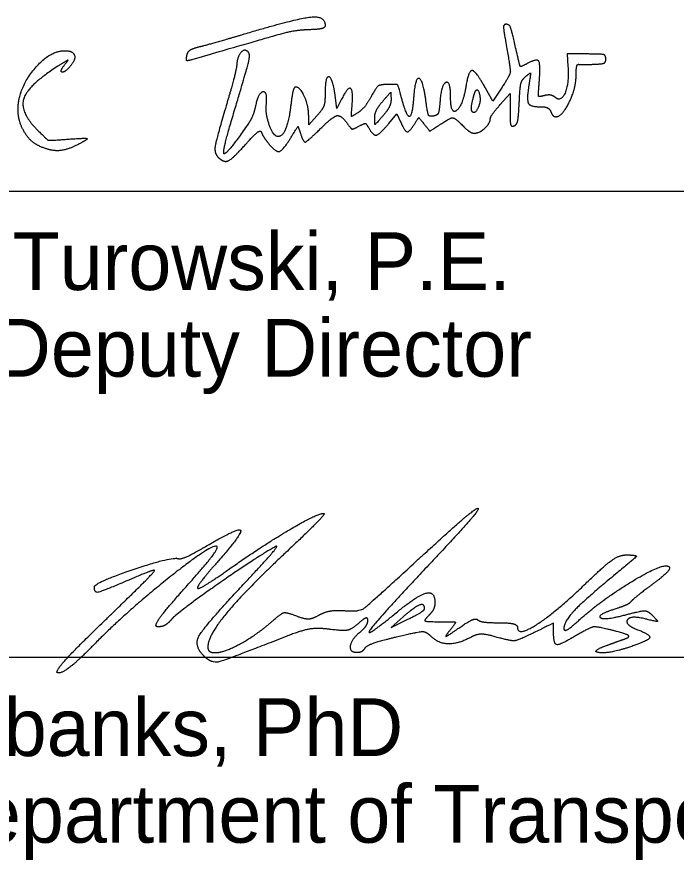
# Model space of a CAD drawing. Extents: x 0 to 34, y 0 to 22.
# Drawn here: x 25.517 to 27.114, y 3.449 to 5.493 of the extents above; entities that cross this region are included whole.
import ezdxf

# ---------------------------------------------------------------- set-up
doc = ezdxf.new("R2010")
doc.units = 0
doc.layers.add('SH_Data', color=7, linetype='Continuous')
doc.layers.add('SH_Text', color=7, linetype='Continuous')

msp = doc.modelspace()

# ---------------------------------------------------------------- linework, layer by layer
at = {"layer": 'SH_Data'}
for p, q in [((24.5279, 5.071), (28.0279, 5.071)), ((24.5279, 3.9416), (28.0279, 3.9416))]:
    msp.add_line(p, q, dxfattribs=at)
at = {"layer": 'SH_Text'}
for p, q in [((25.9287, 5.3994), (25.9287, 5.3994)), ((25.5689, 5.1811), (25.5689, 5.1811)), ((26.5045, 4.0588), (26.5045, 4.0588)), ((25.7273, 4.0277), (25.7273, 4.0277))]:
    msp.add_line(p, q, dxfattribs=at)
for points in [[(26.8966, 5.4031), (26.8497, 5.4031), (26.8519, 5.3729)], [(26.6905, 5.3201), (26.6698, 5.2889), (26.6524, 5.3199)], [(26.3033, 5.2933), (26.2923, 5.2711), (26.2879, 5.3024)], [(26.6875, 5.2803), (26.7115, 5.3076), (26.7115, 5.2667)], [(26.2437, 5.2535), (26.224, 5.2311), (26.2237, 5.2535)], [(26.4178, 5.2345), (26.4375, 5.2579), (26.4463, 5.2385)], [(26.4527, 4.0391), (26.4232, 4.0135), (26.4638, 4.0331)]]:
    msp.add_lwpolyline(points, dxfattribs=at)
for points in [[(26.0677, 5.4516), (26.1931, 5.4889), (26.2635, 5.4963), (26.2635, 5.4721)], [(26.2253, 5.4619), (26.1933, 5.461), (26.1405, 5.4474), (25.9407, 5.3891)], [(26.2635, 5.4721), (26.2635, 5.4668), (26.2477, 5.4626), (26.2253, 5.4619)], [(26.7022, 5.4751), (26.6963, 5.4751), (26.6954, 5.4639), (26.6995, 5.4411)], [(26.7309, 5.3929), (26.7165, 5.4567), (26.7101, 5.4751), (26.7022, 5.4751)], [(25.9595, 5.4209), (25.9749, 5.4246), (26.0236, 5.4384), (26.0677, 5.4516)], [(26.6995, 5.4411), (26.7128, 5.3662), (26.7117, 5.3522), (26.6905, 5.3201)], [(25.9287, 5.3994), (25.9304, 5.4085), (25.9422, 5.4166), (25.9595, 5.4209)], [(25.5197, 5.2687), (25.5201, 5.3178), (25.5945, 5.4111), (25.6332, 5.4111)], [(25.6332, 5.4111), (25.6521, 5.4111), (25.6602, 5.3904), (25.6474, 5.375)], [(25.9407, 5.3891), (25.9295, 5.3858), (25.9266, 5.3884), (25.9287, 5.3994)], [(26.039, 5.2493), (26.0736, 5.3647), (26.0827, 5.4025), (26.0773, 5.4079)], [(26.0773, 5.4079), (26.0685, 5.4167), (26.0512, 5.3976), (26.0495, 5.3774)], [(26.9435, 5.3911), (26.9435, 5.4004), (26.9329, 5.4031), (26.8966, 5.4031)], [(25.6195, 5.3756), (25.5442, 5.3281), (25.5228, 5.2625), (25.5678, 5.2175)], [(25.6325, 5.3769), (25.6421, 5.389), (25.6405, 5.3889), (25.6195, 5.3756)], [(25.6474, 5.375), (25.6335, 5.3582), (25.6192, 5.3601), (25.6325, 5.3769)], [(26.0495, 5.3774), (26.0487, 5.3672), (26.0371, 5.3221), (26.0237, 5.2772)], [(26.7525, 5.3796), (26.7378, 5.3717), (26.7353, 5.3733), (26.7309, 5.3929)], [(26.7823, 5.3354), (26.7857, 5.379), (26.7766, 5.3925), (26.7525, 5.3796)], [(26.8715, 5.3498), (26.8715, 5.3659), (26.8742, 5.3786), (26.8775, 5.3781)], [(26.8775, 5.3781), (26.8808, 5.3776), (26.897, 5.3776), (26.9135, 5.3781)], [(26.9135, 5.3781), (26.9344, 5.3788), (26.9435, 5.3827), (26.9435, 5.3911)], [(26.6524, 5.3199), (26.629, 5.3618), (26.6111, 5.3643), (26.605, 5.3267)], [(26.7492, 5.3484), (26.7609, 5.358), (26.7616, 5.356), (26.7571, 5.3276)], [(26.8519, 5.3729), (26.8547, 5.3329), (26.8354, 5.2858), (26.8211, 5.2978)], [(26.2879, 5.3024), (26.2818, 5.3459), (26.2635, 5.3502), (26.2635, 5.3082)], [(26.5075, 5.2906), (26.5005, 5.3416), (26.4815, 5.3462), (26.4779, 5.2977)], [(26.5675, 5.2991), (26.5675, 5.3385), (26.5449, 5.3297), (26.5419, 5.2891)], [(26.7338, 5.285), (26.7355, 5.3217), (26.7401, 5.3409), (26.7492, 5.3484)], [(26.795, 5.3023), (26.7808, 5.2986), (26.7796, 5.3017), (26.7823, 5.3354)], [(26.8229, 5.2511), (26.8376, 5.2511), (26.8715, 5.3198), (26.8715, 5.3498)], [(26.1924, 5.3231), (26.1887, 5.3231), (26.1837, 5.3058), (26.1812, 5.2847)], [(26.2237, 5.2535), (26.2235, 5.2779), (26.2031, 5.3231), (26.1924, 5.3231)], [(26.3291, 5.2799), (26.332, 5.3161), (26.3181, 5.3233), (26.3033, 5.2933)], [(26.4155, 5.3293), (26.3961, 5.3288), (26.3878, 5.3226), (26.3747, 5.2994)], [(26.4493, 5.2944), (26.4407, 5.3269), (26.4377, 5.3299), (26.4155, 5.3293)], [(26.605, 5.3267), (26.5969, 5.277), (26.5675, 5.2553), (26.5675, 5.2991)], [(26.6205, 5.2891), (26.6234, 5.3012), (26.6269, 5.3125), (26.6284, 5.3142)], [(26.6284, 5.3142), (26.634, 5.3207), (26.641, 5.2905), (26.6366, 5.2791)], [(26.7571, 5.3276), (26.7513, 5.2915), (26.7608, 5.2751), (26.7876, 5.2751)], [(26.1212, 5.2814), (26.1245, 5.3132), (26.1015, 5.3096), (26.0949, 5.2773)], [(26.2635, 5.3082), (26.2635, 5.2853), (26.2578, 5.2694), (26.2437, 5.2535)], [(26.3747, 5.2994), (26.3657, 5.2833), (26.3512, 5.2657), (26.3425, 5.2603)], [(26.4032, 5.2886), (26.4221, 5.3101), (26.423, 5.3103), (26.4232, 5.2935)], [(26.4232, 5.2935), (26.4234, 5.2838), (26.4146, 5.2658), (26.4037, 5.2535)], [(26.4779, 5.2977), (26.4746, 5.2526), (26.461, 5.251), (26.4493, 5.2944)], [(26.8211, 5.2978), (26.8153, 5.3025), (26.8036, 5.3045), (26.795, 5.3023)], [(26.0237, 5.2772), (25.9997, 5.1962), (25.9946, 5.1626), (26.0048, 5.1524)], [(26.0949, 5.2773), (26.092, 5.2631), (26.0839, 5.2433), (26.0769, 5.2333)], [(26.1498, 5.2031), (26.1386, 5.2031), (26.1187, 5.2575), (26.1212, 5.2814)], [(26.1812, 5.2847), (26.1762, 5.2426), (26.161, 5.2031), (26.1498, 5.2031)], [(26.3425, 5.2603), (26.3277, 5.2511), (26.3269, 5.2524), (26.3291, 5.2799)], [(26.3837, 5.2486), (26.3836, 5.2583), (26.3924, 5.2763), (26.4032, 5.2886)], [(26.5263, 5.2527), (26.516, 5.2507), (26.5119, 5.2591), (26.5075, 5.2906)], [(26.5419, 5.2891), (26.5402, 5.2652), (26.5356, 5.2545), (26.5263, 5.2527)], [(26.6366, 5.2791), (26.6283, 5.2575), (26.6149, 5.2658), (26.6205, 5.2891)], [(26.6635, 5.2452), (26.6635, 5.2495), (26.6743, 5.2652), (26.6875, 5.2803)], [(26.7215, 5.229), (26.7278, 5.2311), (26.7324, 5.2518), (26.7338, 5.285)], [(26.7876, 5.2751), (26.7976, 5.2751), (26.8078, 5.2697), (26.8104, 5.2631)], [(25.5689, 5.1811), (25.5476, 5.1913), (25.5194, 5.2416), (25.5197, 5.2687)], [(26.2518, 5.2217), (26.2818, 5.2517), (26.3025, 5.2555), (26.318, 5.2338)], [(26.4037, 5.2535), (26.3849, 5.232), (26.384, 5.2318), (26.3837, 5.2486)], [(26.7115, 5.2667), (26.7115, 5.2375), (26.7144, 5.2267), (26.7215, 5.229)], [(26.8104, 5.2631), (26.8129, 5.2565), (26.8185, 5.2511), (26.8229, 5.2511)], [(26.0769, 5.2333), (26.0249, 5.1586), (26.0132, 5.1635), (26.039, 5.2493)], [(26.318, 5.2338), (26.3265, 5.2217), (26.3315, 5.2206), (26.3451, 5.2279)], [(26.3451, 5.2279), (26.3585, 5.2351), (26.3633, 5.2343), (26.3691, 5.224)], [(26.3691, 5.224), (26.3798, 5.2048), (26.3957, 5.2082), (26.4178, 5.2345)], [(26.4463, 5.2385), (26.4569, 5.2151), (26.4681, 5.2138), (26.4808, 5.2342)], [(26.4808, 5.2342), (26.49, 5.249), (26.4907, 5.2489), (26.5039, 5.2326)], [(26.5039, 5.2326), (26.5173, 5.216), (26.5176, 5.216), (26.5405, 5.2312)], [(26.5405, 5.2312), (26.5671, 5.249), (26.5784, 5.2481), (26.5999, 5.2266)], [(26.6249, 5.2111), (26.6366, 5.2111), (26.6635, 5.2349), (26.6635, 5.2452)], [(25.5678, 5.2175), (25.5906, 5.1948), (25.5952, 5.1934), (25.6398, 5.1966)], [(26.0719, 5.1851), (26.0918, 5.2074), (26.1072, 5.219), (26.1092, 5.2132)], [(26.1092, 5.2132), (26.1112, 5.2077), (26.1191, 5.1954), (26.1269, 5.1858)], [(26.1826, 5.2036), (26.197, 5.2271), (26.1982, 5.2276), (26.2032, 5.2119)], [(26.2032, 5.2119), (26.2106, 5.1887), (26.2208, 5.1907), (26.2518, 5.2217)], [(26.5999, 5.2266), (26.6085, 5.2181), (26.6197, 5.2111), (26.6249, 5.2111)], [(25.6398, 5.1966), (25.666, 5.1985), (25.6875, 5.199), (25.6875, 5.1978)], [(25.6875, 5.1978), (25.6875, 5.1965), (25.6769, 5.19), (25.6639, 5.1833)], [(26.1269, 5.1858), (26.1444, 5.1642), (26.1621, 5.1698), (26.1826, 5.2036)], [(25.6639, 5.1833), (25.6366, 5.1692), (25.5956, 5.1682), (25.5689, 5.1811)], [(26.0048, 5.1524), (26.0182, 5.139), (26.0408, 5.15), (26.0719, 5.1851)], [(26.4869, 4.1762), (26.5619, 4.2453), (26.6279, 4.302), (26.6336, 4.302)], [(26.6336, 4.302), (26.6394, 4.3021), (26.5873, 4.242), (26.518, 4.1684)], [(26.0326, 4.1558), (26.1131, 4.2124), (26.2445, 4.2897), (26.2602, 4.2897)], [(26.2602, 4.2897), (26.265, 4.2897), (26.2237, 4.2471), (26.1684, 4.195)], [(25.9736, 4.2093), (26.0524, 4.2555), (26.0646, 4.2423), (26.0054, 4.175)], [(26.0017, 4.2091), (25.9921, 4.2187), (25.7824, 4.0518), (25.7045, 3.9725)], [(26.142, 4.2086), (26.0929, 4.1809), (25.9046, 4.0486), (25.8914, 4.0327)], [(25.908, 4.1801), (25.9136, 4.1783), (25.9431, 4.1914), (25.9736, 4.2093)], [(25.9239, 4.1087), (25.9702, 4.1605), (26.0052, 4.2056), (26.0017, 4.2091)], [(26.1684, 4.195), (26.0687, 4.1013), (25.9795, 3.9931), (25.9795, 3.9661)], [(26.0768, 4.1297), (26.123, 4.179), (26.1523, 4.2145), (26.142, 4.2086)], [(25.7047, 4.1116), (25.7049, 4.1221), (25.8923, 4.1853), (25.908, 4.1801)], [(26.0054, 4.175), (25.9774, 4.1431), (25.9545, 4.1135), (25.9545, 4.109)], [(26.3119, 4.0539), (26.3453, 4.051), (26.3688, 4.0675), (26.4869, 4.1762)], [(26.8951, 4.12), (26.9403, 4.1638), (26.9774, 4.1895), (26.9951, 4.1891)], [(26.9951, 4.1891), (27.0194, 4.1886), (27.0156, 4.1823), (26.967, 4.1423)], [(25.7273, 4.0277), (25.7983, 4.0962), (25.8537, 4.1522), (25.8502, 4.1522)], [(25.8502, 4.1522), (25.8468, 4.1522), (25.8178, 4.1409), (25.7857, 4.1272)], [(25.9545, 4.109), (25.9545, 4.1046), (25.9896, 4.1256), (26.0326, 4.1558)], [(26.518, 4.1684), (26.3885, 4.0308), (26.3564, 3.9835), (26.4386, 4.0513)], [(26.8763, 4.0288), (26.93, 4.0776), (27.0769, 4.1676), (27.0938, 4.162)], [(27.0938, 4.162), (27.1022, 4.1592), (27.087, 4.1405), (27.0599, 4.1203)], [(25.9697, 3.9441), (25.9445, 3.9693), (25.9734, 4.0194), (26.0768, 4.1297)], [(26.967, 4.1423), (26.8929, 4.0813), (26.842, 4.0278), (26.842, 4.011)], [(25.7857, 4.1272), (25.7231, 4.1004), (25.7044, 4.0967), (25.7047, 4.1116)], [(25.8581, 4.0147), (25.8478, 4.0147), (25.8767, 4.056), (25.9239, 4.1087)], [(26.7295, 4.0132), (26.7295, 3.9904), (26.8248, 4.0518), (26.8951, 4.12)], [(27.0599, 4.1203), (27.0328, 4.1001), (27.0079, 4.0801), (27.0045, 4.0758)], [(26.4386, 4.0513), (26.487, 4.0912), (26.5295, 4.1015), (26.5295, 4.0734)], [(26.5045, 4.0588), (26.5045, 4.0722), (26.4804, 4.0631), (26.4527, 4.0391)], [(26.5295, 4.0734), (26.5295, 4.0645), (26.5227, 4.0504), (26.5145, 4.0422)], [(27.0045, 4.0758), (27.001, 4.0716), (26.9856, 4.0641), (26.9701, 4.0593)], [(26.137, 4.0297), (26.1573, 4.0477), (26.1701, 4.0504), (26.1939, 4.0413)], [(26.2489, 4.0434), (26.2623, 4.0509), (26.2906, 4.0557), (26.3119, 4.0539)], [(26.4638, 4.0331), (26.4862, 4.044), (26.5045, 4.0555), (26.5045, 4.0588)], [(26.9701, 4.0593), (26.9206, 4.0438), (26.9401, 4.0302), (26.9919, 4.044)], [(26.9919, 4.044), (27.0302, 4.0542), (27.0455, 4.0536), (27.0575, 4.0414)], [(25.617, 3.9029), (25.6067, 3.9031), (25.6563, 3.9593), (25.7273, 4.0277)], [(25.8914, 4.0327), (25.8831, 4.0228), (25.8682, 4.0147), (25.8581, 4.0147)], [(25.9975, 3.9522), (26.0192, 3.9522), (26.1006, 3.9974), (26.137, 4.0297)], [(26.1939, 4.0413), (26.2141, 4.0337), (26.2329, 4.0344), (26.2489, 4.0434)], [(26.367, 4.0307), (26.367, 4.0378), (26.3568, 4.0344), (26.3444, 4.0231)], [(26.3482, 4.0022), (26.3585, 4.0107), (26.367, 4.0236), (26.367, 4.0307)], [(26.5145, 4.0422), (26.5028, 4.0305), (26.5087, 4.0272), (26.541, 4.0272)], [(26.541, 4.0272), (26.5785, 4.0272), (26.5809, 4.0251), (26.5654, 4.0058)], [(26.5871, 4.0117), (26.6085, 4.0267), (26.6293, 4.0357), (26.6332, 4.0318)], [(26.6332, 4.0318), (26.6371, 4.0279), (26.6604, 4.0247), (26.6849, 4.0247)], [(26.842, 4.011), (26.842, 4.0036), (26.8574, 4.0116), (26.8763, 4.0288)], [(27.0388, 4.0339), (27.0021, 4.043), (26.9889, 4.0199), (27.0232, 4.0067)], [(27.0575, 4.0414), (27.0702, 4.0285), (27.0666, 4.027), (27.0388, 4.0339)], [(26.2749, 4.0087), (26.2457, 4.0125), (26.2058, 4.006), (26.1693, 3.9916)], [(26.3444, 4.0231), (26.3287, 4.009), (26.3075, 4.0045), (26.2749, 4.0087)], [(26.5654, 4.0058), (26.5533, 3.9908), (26.5598, 3.9926), (26.5871, 4.0117)], [(26.6849, 4.0247), (26.7094, 4.0247), (26.7295, 4.0195), (26.7295, 4.0132)], [(26.817, 4.0006), (26.817, 4.0235), (26.8159, 4.0235), (26.7698, 4.0007)], [(26.9621, 4.0056), (26.9233, 4.0155), (26.9065, 4.0139), (26.8789, 3.9976)], [(27.0232, 4.0067), (27.0538, 3.995), (27.0449, 3.9801), (26.9981, 3.9647)], [(26.1693, 3.9916), (26.0233, 3.9339), (25.9882, 3.9256), (25.9697, 3.9441)], [(26.3412, 3.9522), (26.3229, 3.9522), (26.3274, 3.9849), (26.3482, 4.0022)], [(26.4355, 3.9896), (26.3972, 3.9804), (26.3629, 3.9683), (26.3594, 3.9626)], [(26.5199, 3.9918), (26.5088, 4.0029), (26.4887, 4.0024), (26.4355, 3.9896)], [(26.6162, 3.9893), (26.5854, 3.9728), (26.5376, 3.9741), (26.5199, 3.9918)], [(26.6807, 3.9893), (26.6538, 3.9971), (26.6307, 3.997), (26.6162, 3.9893)], [(26.7698, 4.0007), (26.7324, 3.9822), (26.7138, 3.9798), (26.6807, 3.9893)], [(26.8789, 3.9976), (26.8339, 3.971), (26.817, 3.9718), (26.817, 4.0006)], [(26.9482, 3.9707), (26.962, 3.9756), (26.9817, 3.9827), (26.992, 3.9864)], [(26.992, 3.9864), (27.0034, 3.9906), (26.9917, 3.9981), (26.9621, 4.0056)], [(25.7045, 3.9725), (25.6667, 3.934), (25.6273, 3.9027), (25.617, 3.9029)], [(25.9795, 3.9661), (25.9795, 3.9585), (25.9876, 3.9522), (25.9975, 3.9522)], [(26.9981, 3.9647), (26.9515, 3.9493), (26.9042, 3.955), (26.9482, 3.9707)], [(26.3594, 3.9626), (26.3559, 3.9569), (26.3477, 3.9522), (26.3412, 3.9522)]]:
    msp.add_open_spline(points, degree=2, dxfattribs=at)

# ---------------------------------------------------------------- texts
for s, p in [('Anthony C. Turowski, P.E.', (24.5279, 4.831)), ('District       Deputy Director', (24.5279, 4.621)), ('Jack Marchbanks, PhD', (24.5279, 3.7016)), ('Director, Department of Transportation', (24.5279, 3.4916))]:
    msp.add_text(s, height=0.14, dxfattribs=at).set_placement(p)

doc.saveas('drawing.dxf')
